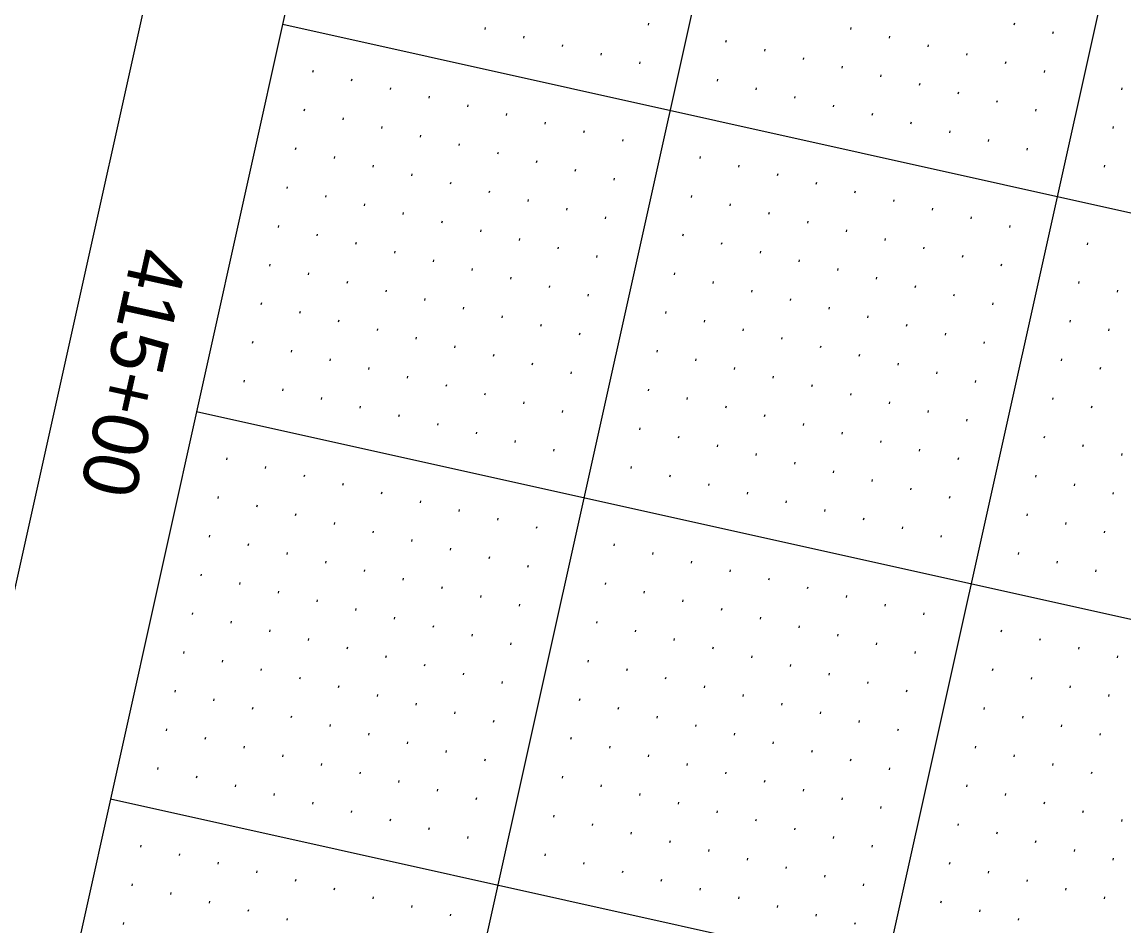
# Model space of a CAD drawing. Extents: x 2149268 to 2150830, y 142155 to 144285.
# Drawn here: x 2149580.1 to 2149719, y 143385.7 to 143499.6 of the extents above; entities that cross this region are included whole.
import ezdxf

# ---------------------------------------------------------------- set-up
doc = ezdxf.new("R2010")
doc.units = 0
for name, color, linetype in [('SHT_Plan_Profile_Sheet_Sta_Txt', 7, 'Continuous'), ('SHT_Profile_Grid_Major', 7, 'Continuous'), ('SHT_Profile_Grid_Minor', 7, 'Continuous'), ('SHT_Sheet_Border', 7, 'Continuous')]:
    doc.layers.add(name, color=color, linetype=linetype)

msp = doc.modelspace()

# ---------------------------------------------------------------- linework, layer by layer
at = {"layer": 'SHT_Profile_Grid_Major'}
for p, q in [((2149767.6, 143964.37), (2149425.74, 142426.92)), ((2149816.41, 143953.52), (2149474.54, 142416.07)), ((2149612.98, 143499.35), (2150101.06, 143390.82)), ((2149602.12, 143450.54), (2150090.2, 143342.01)), ((2149591.27, 143401.73), (2150079.35, 143293.2))]:
    msp.add_line(p, q, dxfattribs=at)
at = {"layer": 'SHT_Profile_Grid_Minor'}
for p, q in [((2149638.49, 143498.92), (2149638.44, 143498.68)), ((2149659.1, 143499.46), (2149659.05, 143499.22)), ((2149684.59, 143498.92), (2149684.54, 143498.67)), ((2149705.2, 143499.46), (2149705.14, 143499.21)), ((2149643.37, 143497.84), (2149643.32, 143497.59)), ((2149689.47, 143497.83), (2149689.42, 143497.59)), ((2149710.08, 143498.37), (2149710.02, 143498.13)), ((2149648.25, 143496.75), (2149648.2, 143496.51)), ((2149668.86, 143497.29), (2149668.81, 143497.05)), ((2149673.74, 143496.21), (2149673.69, 143495.96)), ((2149694.35, 143496.75), (2149694.3, 143496.5)), ((2149653.13, 143495.67), (2149653.08, 143495.42)), ((2149678.62, 143495.12), (2149678.57, 143494.88)), ((2149699.23, 143495.66), (2149699.18, 143495.42)), ((2149616.8, 143493.5), (2149616.74, 143493.26)), ((2149658.01, 143494.58), (2149657.96, 143494.34)), ((2149683.5, 143494.04), (2149683.45, 143493.79)), ((2149704.11, 143494.58), (2149704.06, 143494.33)), ((2149708.99, 143493.49), (2149708.94, 143493.25)), ((2149621.68, 143492.42), (2149621.62, 143492.17)), ((2149667.78, 143492.41), (2149667.72, 143492.17)), ((2149688.39, 143492.95), (2149688.33, 143492.71)), ((2149626.56, 143491.33), (2149626.51, 143491.09)), ((2149672.66, 143491.33), (2149672.6, 143491.08)), ((2149693.27, 143491.87), (2149693.21, 143491.62)), ((2149698.15, 143490.78), (2149698.09, 143490.54)), ((2149718.76, 143491.32), (2149718.7, 143491.08)), ((2149631.44, 143490.25), (2149631.39, 143490)), ((2149636.32, 143489.16), (2149636.27, 143488.92)), ((2149677.54, 143490.24), (2149677.48, 143490)), ((2149682.42, 143489.15), (2149682.36, 143488.91)), ((2149703.03, 143489.69), (2149702.97, 143489.45)), ((2149615.71, 143488.62), (2149615.66, 143488.38)), ((2149641.2, 143488.08), (2149641.15, 143487.83)), ((2149687.3, 143488.07), (2149687.25, 143487.83)), ((2149707.91, 143488.61), (2149707.85, 143488.37)), ((2149620.59, 143487.54), (2149620.54, 143487.29)), ((2149625.47, 143486.45), (2149625.42, 143486.21)), ((2149646.08, 143486.99), (2149646.03, 143486.75)), ((2149692.18, 143486.98), (2149692.13, 143486.74)), ((2149717.67, 143486.44), (2149717.62, 143486.19)), ((2149630.36, 143485.37), (2149630.3, 143485.12)), ((2149650.96, 143485.9), (2149650.91, 143485.66)), ((2149697.06, 143485.9), (2149697.01, 143485.65)), ((2149614.63, 143483.74), (2149614.57, 143483.5)), ((2149635.24, 143484.28), (2149635.18, 143484.04)), ((2149655.84, 143484.82), (2149655.79, 143484.58)), ((2149701.94, 143484.81), (2149701.89, 143484.57)), ((2149706.82, 143483.73), (2149706.77, 143483.48)), ((2149619.51, 143482.65), (2149619.45, 143482.41)), ((2149640.12, 143483.19), (2149640.06, 143482.95)), ((2149665.61, 143482.65), (2149665.55, 143482.4)), ((2149624.39, 143481.57), (2149624.33, 143481.33)), ((2149645, 143482.11), (2149644.94, 143481.87)), ((2149649.88, 143481.02), (2149649.82, 143480.78)), ((2149670.49, 143481.56), (2149670.43, 143481.32)), ((2149716.58, 143481.56), (2149716.53, 143481.31)), ((2149629.27, 143480.48), (2149629.22, 143480.24)), ((2149654.76, 143479.94), (2149654.7, 143479.69)), ((2149675.37, 143480.48), (2149675.31, 143480.23)), ((2149613.54, 143478.86), (2149613.49, 143478.62)), ((2149634.15, 143479.4), (2149634.1, 143479.16)), ((2149639.03, 143478.31), (2149638.98, 143478.07)), ((2149680.25, 143479.39), (2149680.19, 143479.15)), ((2149685.13, 143478.31), (2149685.07, 143478.06)), ((2149618.42, 143477.77), (2149618.37, 143477.53)), ((2149623.3, 143476.69), (2149623.25, 143476.44)), ((2149643.91, 143477.23), (2149643.86, 143476.98)), ((2149664.52, 143477.77), (2149664.47, 143477.52)), ((2149669.4, 143476.68), (2149669.35, 143476.44)), ((2149690.01, 143477.22), (2149689.96, 143476.98)), ((2149628.18, 143475.6), (2149628.13, 143475.36)), ((2149648.79, 143476.14), (2149648.74, 143475.9)), ((2149674.28, 143475.6), (2149674.23, 143475.35)), ((2149694.89, 143476.14), (2149694.84, 143475.89)), ((2149612.46, 143473.98), (2149612.4, 143473.73)), ((2149633.07, 143474.52), (2149633.01, 143474.27)), ((2149653.67, 143475.06), (2149653.62, 143474.81)), ((2149679.16, 143474.51), (2149679.11, 143474.27)), ((2149699.77, 143475.05), (2149699.72, 143474.81)), ((2149704.65, 143473.97), (2149704.6, 143473.72)), ((2149617.34, 143472.89), (2149617.28, 143472.65)), ((2149637.95, 143473.43), (2149637.89, 143473.19)), ((2149663.44, 143472.89), (2149663.38, 143472.64)), ((2149684.04, 143473.43), (2149683.99, 143473.18)), ((2149622.22, 143471.81), (2149622.16, 143471.56)), ((2149642.83, 143472.35), (2149642.77, 143472.1)), ((2149647.71, 143471.26), (2149647.65, 143471.02)), ((2149668.32, 143471.8), (2149668.26, 143471.56)), ((2149688.92, 143472.34), (2149688.87, 143472.1)), ((2149693.81, 143471.26), (2149693.75, 143471.01)), ((2149714.41, 143471.8), (2149714.36, 143471.55)), ((2149627.1, 143470.72), (2149627.05, 143470.48)), ((2149652.59, 143470.18), (2149652.53, 143469.93)), ((2149673.2, 143470.72), (2149673.14, 143470.47)), ((2149698.69, 143470.17), (2149698.63, 143469.93)), ((2149611.37, 143469.1), (2149611.32, 143468.85)), ((2149631.98, 143469.64), (2149631.93, 143469.39)), ((2149636.86, 143468.55), (2149636.81, 143468.31)), ((2149678.08, 143469.63), (2149678.02, 143469.39)), ((2149682.96, 143468.55), (2149682.9, 143468.3)), ((2149703.57, 143469.09), (2149703.51, 143468.84)), ((2149616.25, 143468.01), (2149616.2, 143467.77)), ((2149621.13, 143466.93), (2149621.08, 143466.68)), ((2149641.74, 143467.47), (2149641.69, 143467.22)), ((2149662.35, 143468.01), (2149662.3, 143467.76)), ((2149687.84, 143467.46), (2149687.79, 143467.22)), ((2149626.01, 143465.84), (2149625.96, 143465.6)), ((2149646.62, 143466.38), (2149646.57, 143466.14)), ((2149667.23, 143466.92), (2149667.18, 143466.68)), ((2149672.11, 143465.84), (2149672.06, 143465.59)), ((2149692.72, 143466.38), (2149692.67, 143466.13)), ((2149713.33, 143466.92), (2149713.27, 143466.67)), ((2149718.21, 143465.83), (2149718.16, 143465.59)), ((2149610.29, 143464.22), (2149610.23, 143463.97)), ((2149630.89, 143464.76), (2149630.84, 143464.51)), ((2149651.5, 143465.3), (2149651.45, 143465.05)), ((2149676.99, 143464.75), (2149676.94, 143464.51)), ((2149697.6, 143465.29), (2149697.55, 143465.05)), ((2149702.48, 143464.21), (2149702.43, 143463.96)), ((2149615.17, 143463.13), (2149615.11, 143462.89)), ((2149635.78, 143463.67), (2149635.72, 143463.43)), ((2149661.26, 143463.13), (2149661.21, 143462.88)), ((2149681.87, 143463.67), (2149681.82, 143463.42)), ((2149620.05, 143462.05), (2149619.99, 143461.8)), ((2149640.66, 143462.59), (2149640.6, 143462.34)), ((2149645.54, 143461.5), (2149645.48, 143461.26)), ((2149666.15, 143462.04), (2149666.09, 143461.8)), ((2149686.75, 143462.58), (2149686.7, 143462.34)), ((2149691.63, 143461.5), (2149691.58, 143461.25)), ((2149712.24, 143462.03), (2149712.19, 143461.79)), ((2149624.93, 143460.96), (2149624.87, 143460.72)), ((2149650.42, 143460.42), (2149650.36, 143460.17)), ((2149671.03, 143460.96), (2149670.97, 143460.71)), ((2149696.52, 143460.41), (2149696.46, 143460.17)), ((2149717.12, 143460.95), (2149717.07, 143460.71)), ((2149609.2, 143459.34), (2149609.15, 143459.09)), ((2149629.81, 143459.88), (2149629.76, 143459.63)), ((2149634.69, 143458.79), (2149634.64, 143458.55)), ((2149675.91, 143459.87), (2149675.85, 143459.63)), ((2149680.79, 143458.78), (2149680.73, 143458.54)), ((2149701.4, 143459.32), (2149701.34, 143459.08)), ((2149614.08, 143458.25), (2149614.03, 143458.01)), ((2149639.57, 143457.71), (2149639.52, 143457.46)), ((2149660.18, 143458.25), (2149660.13, 143458)), ((2149685.67, 143457.7), (2149685.61, 143457.46)), ((2149618.96, 143457.17), (2149618.91, 143456.92)), ((2149623.84, 143456.08), (2149623.79, 143455.84)), ((2149644.45, 143456.62), (2149644.4, 143456.38)), ((2149665.06, 143457.16), (2149665.01, 143456.92)), ((2149669.94, 143456.07), (2149669.89, 143455.83)), ((2149690.55, 143456.61), (2149690.5, 143456.37)), ((2149711.16, 143457.15), (2149711.1, 143456.91)), ((2149716.04, 143456.07), (2149715.98, 143455.82)), ((2149608.12, 143454.46), (2149608.06, 143454.21)), ((2149628.72, 143455), (2149628.67, 143454.75)), ((2149649.33, 143455.53), (2149649.28, 143455.29)), ((2149674.82, 143454.99), (2149674.77, 143454.75)), ((2149695.43, 143455.53), (2149695.38, 143455.28)), ((2149700.31, 143454.44), (2149700.26, 143454.2)), ((2149613, 143453.37), (2149612.94, 143453.13)), ((2149633.61, 143453.91), (2149633.55, 143453.67)), ((2149659.09, 143453.36), (2149659.04, 143453.12)), ((2149679.7, 143453.9), (2149679.65, 143453.66)), ((2149617.88, 143452.28), (2149617.82, 143452.04)), ((2149638.49, 143452.82), (2149638.43, 143452.58)), ((2149643.37, 143451.74), (2149643.31, 143451.5)), ((2149663.98, 143452.28), (2149663.92, 143452.03)), ((2149684.58, 143452.82), (2149684.53, 143452.57)), ((2149689.46, 143451.73), (2149689.41, 143451.49)), ((2149710.07, 143452.27), (2149710.02, 143452.03)), ((2149622.76, 143451.2), (2149622.7, 143450.96)), ((2149648.25, 143450.65), (2149648.19, 143450.41)), ((2149668.86, 143451.19), (2149668.8, 143450.95)), ((2149694.35, 143450.65), (2149694.29, 143450.4)), ((2149714.95, 143451.19), (2149714.9, 143450.94)), ((2149627.64, 143450.11), (2149627.58, 143449.87)), ((2149632.52, 143449.03), (2149632.47, 143448.79)), ((2149673.74, 143450.11), (2149673.68, 143449.86)), ((2149678.62, 143449.02), (2149678.56, 143448.78)), ((2149699.23, 143449.56), (2149699.17, 143449.32)), ((2149637.4, 143447.94), (2149637.35, 143447.7)), ((2149658.01, 143448.48), (2149657.95, 143448.24)), ((2149683.5, 143447.94), (2149683.44, 143447.69)), ((2149642.28, 143446.86), (2149642.23, 143446.61)), ((2149662.89, 143447.4), (2149662.84, 143447.15)), ((2149667.77, 143446.31), (2149667.72, 143446.07)), ((2149688.38, 143446.85), (2149688.32, 143446.61)), ((2149708.99, 143447.39), (2149708.93, 143447.15)), ((2149713.87, 143446.31), (2149713.81, 143446.06)), ((2149647.16, 143445.77), (2149647.11, 143445.53)), ((2149672.65, 143445.23), (2149672.6, 143444.98)), ((2149693.26, 143445.77), (2149693.21, 143445.52)), ((2149718.75, 143445.22), (2149718.69, 143444.98)), ((2149605.95, 143444.69), (2149605.89, 143444.45)), ((2149610.83, 143443.61), (2149610.77, 143443.36)), ((2149656.92, 143443.6), (2149656.87, 143443.36)), ((2149677.53, 143444.14), (2149677.48, 143443.9)), ((2149698.14, 143444.68), (2149698.09, 143444.44)), ((2149615.71, 143442.52), (2149615.65, 143442.28)), ((2149661.8, 143442.52), (2149661.75, 143442.27)), ((2149682.41, 143443.06), (2149682.36, 143442.81)), ((2149687.29, 143441.97), (2149687.24, 143441.73)), ((2149707.9, 143442.51), (2149707.85, 143442.27)), ((2149620.59, 143441.44), (2149620.53, 143441.19)), ((2149666.69, 143441.43), (2149666.63, 143441.19)), ((2149692.17, 143440.89), (2149692.12, 143440.64)), ((2149712.78, 143441.43), (2149712.73, 143441.18)), ((2149604.86, 143439.81), (2149604.81, 143439.57)), ((2149625.47, 143440.35), (2149625.41, 143440.11)), ((2149630.35, 143439.27), (2149630.29, 143439.02)), ((2149671.57, 143440.35), (2149671.51, 143440.1)), ((2149676.45, 143439.26), (2149676.39, 143439.02)), ((2149697.06, 143439.8), (2149697, 143439.56)), ((2149717.66, 143440.34), (2149717.61, 143440.1)), ((2149609.74, 143438.73), (2149609.69, 143438.48)), ((2149635.23, 143438.18), (2149635.18, 143437.94)), ((2149681.33, 143438.18), (2149681.27, 143437.93)), ((2149614.62, 143437.64), (2149614.57, 143437.4)), ((2149619.5, 143436.56), (2149619.45, 143436.31)), ((2149640.11, 143437.1), (2149640.06, 143436.85)), ((2149686.21, 143437.09), (2149686.15, 143436.85)), ((2149706.82, 143437.63), (2149706.76, 143437.39)), ((2149711.7, 143436.55), (2149711.64, 143436.3)), ((2149624.38, 143435.47), (2149624.33, 143435.23)), ((2149644.99, 143436.01), (2149644.94, 143435.77)), ((2149691.09, 143436.01), (2149691.04, 143435.76)), ((2149716.58, 143435.46), (2149716.52, 143435.22)), ((2149603.77, 143434.93), (2149603.72, 143434.69)), ((2149608.66, 143433.85), (2149608.6, 143433.6)), ((2149629.26, 143434.39), (2149629.21, 143434.14)), ((2149654.75, 143433.84), (2149654.7, 143433.6)), ((2149695.97, 143434.92), (2149695.92, 143434.68)), ((2149613.54, 143432.76), (2149613.48, 143432.52)), ((2149634.14, 143433.3), (2149634.09, 143433.06)), ((2149639.03, 143432.22), (2149638.97, 143431.97)), ((2149659.63, 143432.76), (2149659.58, 143432.51)), ((2149705.73, 143432.75), (2149705.68, 143432.51)), ((2149618.42, 143431.68), (2149618.36, 143431.43)), ((2149643.91, 143431.13), (2149643.85, 143430.89)), ((2149664.51, 143431.67), (2149664.46, 143431.43)), ((2149710.61, 143431.66), (2149710.56, 143431.42)), ((2149602.69, 143430.05), (2149602.64, 143429.81)), ((2149623.3, 143430.59), (2149623.24, 143430.35)), ((2149628.18, 143429.51), (2149628.12, 143429.26)), ((2149669.4, 143430.59), (2149669.34, 143430.34)), ((2149674.28, 143429.5), (2149674.22, 143429.26)), ((2149715.49, 143430.58), (2149715.44, 143430.34)), ((2149607.57, 143428.97), (2149607.52, 143428.72)), ((2149633.06, 143428.42), (2149633.01, 143428.18)), ((2149653.67, 143428.96), (2149653.61, 143428.72)), ((2149679.16, 143428.41), (2149679.1, 143428.17)), ((2149612.45, 143427.88), (2149612.4, 143427.64)), ((2149617.33, 143426.8), (2149617.28, 143426.55)), ((2149637.94, 143427.34), (2149637.89, 143427.09)), ((2149658.55, 143427.88), (2149658.49, 143427.63)), ((2149663.43, 143426.79), (2149663.38, 143426.55)), ((2149684.04, 143427.33), (2149683.98, 143427.09)), ((2149622.21, 143425.71), (2149622.16, 143425.47)), ((2149642.82, 143426.25), (2149642.77, 143426.01)), ((2149668.31, 143425.7), (2149668.26, 143425.46)), ((2149688.92, 143426.24), (2149688.86, 143426)), ((2149601.6, 143425.17), (2149601.55, 143424.93)), ((2149606.48, 143424.09), (2149606.43, 143423.84)), ((2149627.09, 143424.63), (2149627.04, 143424.38)), ((2149652.58, 143424.08), (2149652.53, 143423.84)), ((2149673.19, 143424.62), (2149673.14, 143424.38)), ((2149693.8, 143425.16), (2149693.75, 143424.91)), ((2149611.37, 143423), (2149611.31, 143422.76)), ((2149631.97, 143423.54), (2149631.92, 143423.3)), ((2149657.46, 143422.99), (2149657.41, 143422.75)), ((2149678.07, 143423.53), (2149678.02, 143423.29)), ((2149703.56, 143422.99), (2149703.51, 143422.74)), ((2149616.25, 143421.91), (2149616.19, 143421.67)), ((2149636.85, 143422.45), (2149636.8, 143422.21)), ((2149641.74, 143421.37), (2149641.68, 143421.13)), ((2149662.34, 143421.91), (2149662.29, 143421.66)), ((2149682.95, 143422.45), (2149682.9, 143422.2)), ((2149687.83, 143421.36), (2149687.78, 143421.12)), ((2149708.44, 143421.9), (2149708.39, 143421.66)), ((2149600.52, 143420.29), (2149600.46, 143420.05)), ((2149621.13, 143420.83), (2149621.07, 143420.59)), ((2149626.01, 143419.74), (2149625.95, 143419.5)), ((2149667.23, 143420.82), (2149667.17, 143420.58)), ((2149672.11, 143419.74), (2149672.05, 143419.49)), ((2149692.71, 143420.28), (2149692.66, 143420.03)), ((2149713.32, 143420.82), (2149713.27, 143420.57)), ((2149718.2, 143419.73), (2149718.15, 143419.49)), ((2149605.4, 143419.2), (2149605.35, 143418.96)), ((2149630.89, 143418.66), (2149630.83, 143418.42)), ((2149651.5, 143419.2), (2149651.44, 143418.95)), ((2149676.99, 143418.65), (2149676.93, 143418.41)), ((2149610.28, 143418.12), (2149610.23, 143417.88)), ((2149615.16, 143417.03), (2149615.11, 143416.79)), ((2149635.77, 143417.57), (2149635.72, 143417.33)), ((2149656.38, 143418.11), (2149656.32, 143417.87)), ((2149661.26, 143417.03), (2149661.2, 143416.78)), ((2149681.87, 143417.57), (2149681.81, 143417.32)), ((2149702.48, 143418.11), (2149702.42, 143417.86)), ((2149707.36, 143417.02), (2149707.3, 143416.78)), ((2149620.04, 143415.95), (2149619.99, 143415.7)), ((2149640.65, 143416.49), (2149640.6, 143416.24)), ((2149666.14, 143415.94), (2149666.09, 143415.7)), ((2149686.75, 143416.48), (2149686.69, 143416.24)), ((2149712.24, 143415.94), (2149712.18, 143415.69)), ((2149599.43, 143415.41), (2149599.38, 143415.17)), ((2149604.31, 143414.32), (2149604.26, 143414.08)), ((2149624.92, 143414.86), (2149624.87, 143414.62)), ((2149650.41, 143414.32), (2149650.36, 143414.07)), ((2149671.02, 143414.86), (2149670.97, 143414.61)), ((2149691.63, 143415.4), (2149691.57, 143415.15)), ((2149717.12, 143414.85), (2149717.06, 143414.61)), ((2149609.2, 143413.24), (2149609.14, 143412.99)), ((2149629.8, 143413.78), (2149629.75, 143413.53)), ((2149655.29, 143413.23), (2149655.24, 143412.99)), ((2149675.9, 143413.77), (2149675.85, 143413.53)), ((2149701.39, 143413.23), (2149701.34, 143412.98)), ((2149614.08, 143412.15), (2149614.02, 143411.91)), ((2149634.68, 143412.69), (2149634.63, 143412.45)), ((2149639.57, 143411.61), (2149639.51, 143411.36)), ((2149660.17, 143412.15), (2149660.12, 143411.9)), ((2149680.78, 143412.69), (2149680.73, 143412.44)), ((2149685.66, 143411.6), (2149685.61, 143411.36)), ((2149706.27, 143412.14), (2149706.22, 143411.9)), ((2149598.35, 143410.53), (2149598.29, 143410.28)), ((2149618.96, 143411.07), (2149618.9, 143410.82)), ((2149623.84, 143409.98), (2149623.78, 143409.74)), ((2149665.05, 143411.06), (2149665, 143410.82)), ((2149690.54, 143410.52), (2149690.49, 143410.27)), ((2149711.15, 143411.06), (2149711.1, 143410.81)), ((2149603.23, 143409.44), (2149603.17, 143409.2)), ((2149628.72, 143408.9), (2149628.66, 143408.65)), ((2149649.33, 143409.44), (2149649.27, 143409.19)), ((2149669.94, 143409.98), (2149669.88, 143409.73)), ((2149674.82, 143408.89), (2149674.76, 143408.65)), ((2149716.03, 143409.97), (2149715.98, 143409.73)), ((2149608.11, 143408.36), (2149608.06, 143408.11)), ((2149612.99, 143407.27), (2149612.94, 143407.03)), ((2149633.6, 143407.81), (2149633.54, 143407.57)), ((2149654.21, 143408.35), (2149654.15, 143408.11)), ((2149659.09, 143407.27), (2149659.03, 143407.02)), ((2149679.7, 143407.81), (2149679.64, 143407.56)), ((2149700.31, 143408.35), (2149700.25, 143408.1)), ((2149705.19, 143407.26), (2149705.13, 143407.02)), ((2149617.87, 143406.19), (2149617.82, 143405.94)), ((2149638.48, 143406.73), (2149638.43, 143406.48)), ((2149663.97, 143406.18), (2149663.91, 143405.94)), ((2149684.58, 143406.72), (2149684.52, 143406.48)), ((2149710.07, 143406.18), (2149710.01, 143405.93)), ((2149597.26, 143405.65), (2149597.21, 143405.4)), ((2149602.14, 143404.56), (2149602.09, 143404.32)), ((2149622.75, 143405.1), (2149622.7, 143404.86)), ((2149648.24, 143404.56), (2149648.19, 143404.31)), ((2149668.85, 143405.1), (2149668.8, 143404.85)), ((2149689.46, 143405.64), (2149689.4, 143405.39)), ((2149714.95, 143405.09), (2149714.89, 143404.85)), ((2149607.02, 143403.48), (2149606.97, 143403.23)), ((2149627.63, 143404.02), (2149627.58, 143403.77)), ((2149653.12, 143403.47), (2149653.07, 143403.23)), ((2149673.73, 143404.01), (2149673.68, 143403.77)), ((2149699.22, 143403.47), (2149699.17, 143403.22)), ((2149611.91, 143402.39), (2149611.85, 143402.15)), ((2149632.51, 143402.93), (2149632.46, 143402.69)), ((2149637.39, 143401.85), (2149637.34, 143401.6)), ((2149658, 143402.39), (2149657.95, 143402.14)), ((2149678.61, 143402.93), (2149678.56, 143402.68)), ((2149683.49, 143401.84), (2149683.44, 143401.6)), ((2149704.1, 143402.38), (2149704.05, 143402.14)), ((2149616.79, 143401.31), (2149616.73, 143401.06)), ((2149662.88, 143401.3), (2149662.83, 143401.06)), ((2149688.37, 143400.75), (2149688.32, 143400.51)), ((2149708.98, 143401.29), (2149708.93, 143401.05)), ((2149621.67, 143400.22), (2149621.61, 143399.98)), ((2149626.55, 143399.14), (2149626.49, 143398.89)), ((2149647.16, 143399.68), (2149647.1, 143399.43)), ((2149667.76, 143400.22), (2149667.71, 143399.97)), ((2149672.65, 143399.13), (2149672.59, 143398.89)), ((2149713.86, 143400.21), (2149713.81, 143399.97)), ((2149718.74, 143399.12), (2149718.69, 143398.88)), ((2149631.43, 143398.05), (2149631.37, 143397.81)), ((2149652.04, 143398.59), (2149651.98, 143398.35)), ((2149656.92, 143397.51), (2149656.86, 143397.26)), ((2149677.53, 143398.04), (2149677.47, 143397.8)), ((2149698.13, 143398.58), (2149698.08, 143398.34)), ((2149703.02, 143397.5), (2149702.96, 143397.26)), ((2149636.31, 143396.97), (2149636.26, 143396.72)), ((2149661.8, 143396.42), (2149661.74, 143396.18)), ((2149682.41, 143396.96), (2149682.35, 143396.72)), ((2149707.9, 143396.41), (2149707.84, 143396.17)), ((2149595.09, 143395.89), (2149595.04, 143395.64)), ((2149599.97, 143394.8), (2149599.92, 143394.56)), ((2149646.07, 143394.79), (2149646.02, 143394.55)), ((2149666.68, 143395.33), (2149666.63, 143395.09)), ((2149687.29, 143395.87), (2149687.23, 143395.63)), ((2149712.78, 143395.33), (2149712.72, 143395.08)), ((2149604.85, 143393.72), (2149604.8, 143393.47)), ((2149650.95, 143393.71), (2149650.9, 143393.47)), ((2149671.56, 143394.25), (2149671.51, 143394.01)), ((2149697.05, 143393.7), (2149697, 143393.46)), ((2149717.66, 143394.24), (2149717.6, 143394)), ((2149609.73, 143392.63), (2149609.68, 143392.39)), ((2149655.83, 143392.62), (2149655.78, 143392.38)), ((2149676.44, 143393.16), (2149676.39, 143392.92)), ((2149681.32, 143392.08), (2149681.27, 143391.83)), ((2149701.93, 143392.62), (2149701.88, 143392.37)), ((2149594.01, 143391.01), (2149593.95, 143390.76)), ((2149614.62, 143391.54), (2149614.56, 143391.3)), ((2149660.71, 143391.54), (2149660.66, 143391.29)), ((2149686.2, 143390.99), (2149686.15, 143390.75)), ((2149706.81, 143391.53), (2149706.76, 143391.29)), ((2149598.89, 143389.92), (2149598.83, 143389.68)), ((2149619.5, 143390.46), (2149619.44, 143390.22)), ((2149624.38, 143389.37), (2149624.32, 143389.13)), ((2149665.59, 143390.45), (2149665.54, 143390.21)), ((2149670.47, 143389.37), (2149670.42, 143389.12)), ((2149711.69, 143390.45), (2149711.64, 143390.2)), ((2149716.57, 143389.36), (2149716.52, 143389.12)), ((2149603.77, 143388.83), (2149603.71, 143388.59)), ((2149629.26, 143388.29), (2149629.2, 143388.04)), ((2149675.36, 143388.28), (2149675.3, 143388.04)), ((2149695.96, 143388.82), (2149695.91, 143388.58)), ((2149608.65, 143387.75), (2149608.6, 143387.51)), ((2149613.53, 143386.66), (2149613.48, 143386.42)), ((2149634.14, 143387.2), (2149634.08, 143386.96)), ((2149680.24, 143387.2), (2149680.18, 143386.95)), ((2149700.85, 143387.74), (2149700.79, 143387.49)), ((2149705.73, 143386.65), (2149705.67, 143386.41)), ((2149592.92, 143386.12), (2149592.87, 143385.88)), ((2149685.12, 143386.11), (2149685.06, 143385.87))]:
    msp.add_line(p, q, dxfattribs=at)
at = {"layer": 'SHT_Sheet_Border'}
msp.add_line((2149718.79, 143975.22), (2149433.9, 142694.01), dxfattribs=at)
msp.add_lwpolyline([(2150726.67, 143751.11), (2150384.81, 142213.66), (2149359.84, 142441.57), (2149701.71, 143979.02)], close=True, dxfattribs=at)

# ---------------------------------------------------------------- texts
at = {"layer": 'SHT_Plan_Profile_Sheet_Sta_Txt'}
msp.add_text('415+00', height=7, rotation=257.4638, dxfattribs=at).set_placement((2149594.24, 143471.51))

doc.saveas('drawing.dxf')
